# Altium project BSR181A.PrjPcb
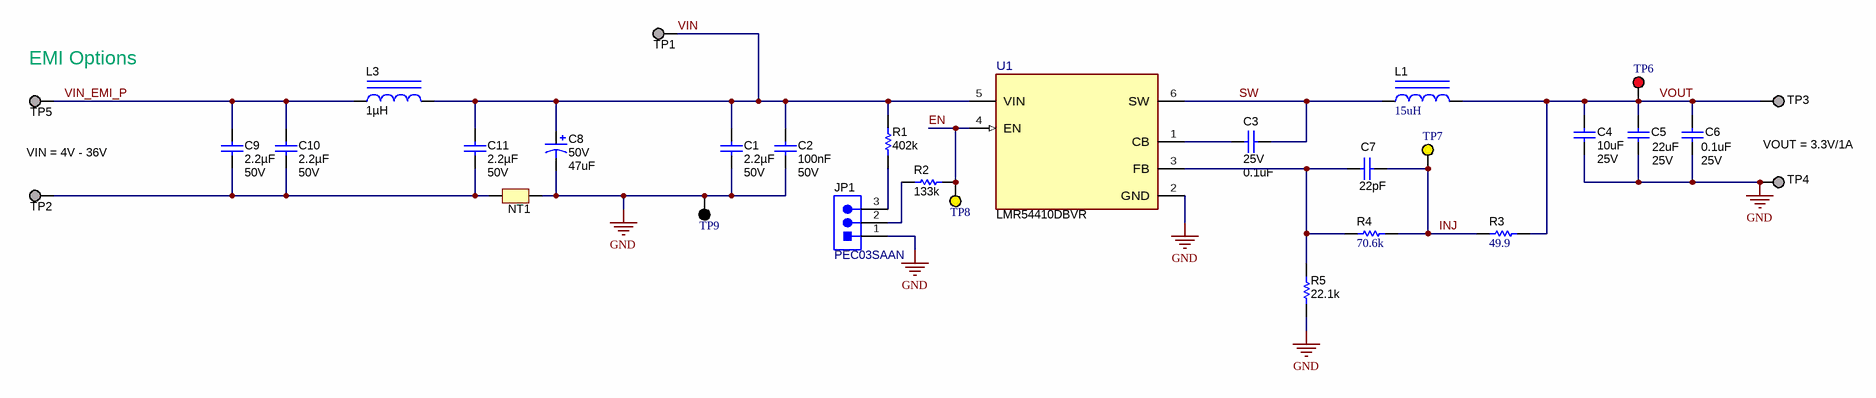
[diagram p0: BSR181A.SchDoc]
CopyrightYear: 2021; PCB_Layout: ElenaGao; PCB_Rev: A1; PRJ_Customer: ENG; PRJ_Engineer: ElenaGao; PRJ_Number: BSR181A; PRJ_Title: LMR54410EVM; SCH_Rev: A1; TechSupport: http://www.ti.com/support; TID: N/A
2 sheets, 46 parts. Net scope: global (net labels, ports and power ports of the same name join across sheets).
Board file: BSR181A.PcbDoc
Sheets:
  BSR181A.SchDoc
  BSR181A_Hardware.SchDoc

## Sheet BSR181A.SchDoc
size 431 x 279 mm; Date: Not shown in title block; ApprovedBy: Not shown in title block; CheckedBy: Not shown in title block; Author: Not shown in title block; CompanyName: Not shown in title block; Engineer: Not shown in title block; Organization: Not shown in title block; Address1: Not shown in title block; Address2: Not shown in title block; Address3: Not shown in title block; Address4: Not shown in title block; DocumentNumber: 2; Revision: Use project parameter SCH_Rev; SheetNumber: 1; SheetTotal: 2; PageSetup: Record=PageOptions¦CenterHorizontal=True¦CenterVertical=True¦PrintScale=1.00¦XCorrection=1.00¦YCorrection=1.00¦PrintKind=0¦BorderSize=5000000¦LeftOffset=0¦BottomOffset=0¦Orientation=2¦PaperLength=1000¦PaperWidth=1000¦Scale=100¦PaperSource=15¦PrintQuality=600¦MediaType=1¦DitherType=10¦PaperKind=Letter¦PrintScaleMode=1

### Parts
C1  Cap_F: 2.2µF  VDC_V: 50V  [0805]  (hidden comment: CGA4J3X7R1H225K125AB)
C2  Cap_F: 100nF  VDC_V: 50V  [0603]  (hidden comment: GCM188R71H104KA57D)
C3  VDC_V: 25V  ValueDisplayed: 0.1uF  [0402S]  (hidden comment: GRM155R71E104KE14D)
C4  Cap_F: 10uF  VDC_V: 25V  [0805]  (hidden comment: GRM21BZ71E106KE15L)
C5  VDC_V: 25V  ValueDisplayed: 22uF  [1812_280]  (hidden comment: CGA8P1X7R1E226M250KC)
C6  Value2: 25V  ValueDisplayed: 0.1uF  [0603]  (hidden comment: C1608X7R1E104K080AA)
C7  ValueDisplayed: 22pF  [0603]  (hidden comment: GRM1885C1H220JA01D)
C8  VDC_V: 50V  ValueDisplayed: 47uF  [CAPSMT_62_F80]  (hidden comment: EMVY500ADA470MF80G)
C9  Cap_F: 2.2µF  VDC_V: 50V  [0805_HV]  (hidden comment: CGA4J3X7R1H225K125AB)
C10  Cap_F: 2.2µF  VDC_V: 50V  [0805_HV]  (hidden comment: CGA4J3X7R1H225K125AB)
C11  Cap_F: 2.2µF  VDC_V: 50V  [0805_HV]  (hidden comment: CGA4J3X7R1H225K125AB)
JP1  PEC03SAAN  [CONN_PEC03SAAN]
L1  ValueDisplayed: 15uH  [WE-LHMI_7050]  (hidden comment: 74437349150)
L3  ValueDisplayed: 1µH  [DFE201612E]  (hidden comment: DFE201612E-1R0M=P2)
NT1  Net-Tie  [Net-Tie_50milWide_30milLong]  (value not drawn)  (net tie, no BOM)
R1  ValueDisplayed: 402k  [0603S]  (hidden comment: CRCW0603402KFKEA)
R2  ValueDisplayed: 133k  [0603S]  (hidden comment: CRCW0603133KFKEA)
R3  ValueDisplayed: 49.9  [0603]  (hidden comment: Resistor)
R4  ValueDisplayed: 70.6k  [0603]  (hidden comment: RT0603BRD0770K6L)
R5  ValueDisplayed: 22.1k  [0603]  (hidden comment: RC0603FR-0722K1L)
TP1  1502-2  [Keystone1502-2]  (value not drawn)
TP2  1502-2  [Keystone1502-2]  (value not drawn)
TP3  1502-2  [Keystone1502-2]  (value not drawn)
TP4  1502-2  [Keystone1502-2]  (value not drawn)
TP5  1502-2  [Keystone1502-2]  (value not drawn)
TP6  5010  [Keystone5010]  (value not drawn)
TP7  5014  [Keystone5014]  (value not drawn)
TP8  5014  [Keystone5014]  (value not drawn)
TP9  5011  [Keystone5011]  (value not drawn)
U1  LMR54410DBVR  [DBV0006A-MFG]

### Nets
GND: C1.2 C2.2 C4.2 C5.2 C6.2 C8.2(-) JP1.1 NT1.2 R5.1 TP4.1 TP9.1 U1.2(GND)
EN: R2.1 TP8.1 U1.4(EN)
INJ: C7.2 R3.2 R4.2 TP7.1
SW: C3.1 L1.1 U1.6(SW)
VIN: C1.1 C2.1 C8.1(+) C11.1 L3.2 R1.2 TP1.1 U1.5(VIN)
VIN_EMI_P: C9.1 C10.1 L3.1 TP5.1
VOUT: C4.1 C5.1 C6.1 L1.2 R3.1 TP3.1 TP6.1
NetC3_2: C3.2 U1.1(CB)
NetC7_1: C7.1 R4.1 R5.2 U1.3(FB)
NetC9_2: C9.2 C10.2 C11.2 NT1.1 TP2.1
NetJP1_2: JP1.2 R2.2
NetJP1_3: JP1.3 R1.1

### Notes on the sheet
- (near TP5) EMI Options
- VIN = 4V - 36V
- VOUT = 3.3V/1A

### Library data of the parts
C1 = CMP-0007977-2: CAP, CERM, 2.2 uF, 50 V, +/- 10%, X7R, AEC-Q200 Grade 1, 0805; Manufacturer: TDK; TaMin_C: -55°C; ESR_ohm: 3.288m; Polarized: N; SizeAreaWB_mm2: 6.75; Value1: 0.003288 ohm; U/M: EA; Value: 2.2uF; TaMax_C: 125°C; SizeZ_mm: 1.45; SizeX_mm: 2; SizeY_mm: 1.25; SizeArea_mm2: 2.5; AEC Qualified: Y; IRMS_A: 3.60029A; AEC Grade: 1; AEC Category: Q200
C2 = CMP-0007144-2: CAP, CERM, 0.1 uF, 50 V, +/- 10%, X7R, 0603; Manufacturer: MuRata; TaMin_C: -55°C; ESR_ohm: 0.02; Polarized: N; SizeAreaWB_mm2: 4.68; Value1: 0.02 ohm; U/M: EA; Value: 0.1uF; TaMax_C: 125°C; SizeZ_mm: 1; SizeX_mm: 1.6; SizeY_mm: 0.8; SizeArea_mm2: 1.28; IRMS_A: 1.84A; AEC Category: Q200
C3 = CMP-0006659-1: CAP, CERM, 0.1 uF, 25 V, +/- 10%, X7R, 0402; Manufacturer: MuRata; TaMin_C: -55°C; Polarized: N; SizeAreaWB_mm2: 3; Value1: Unknown; U/M: EA; Value: 0.1uF; TaMax_C: 125°C; SizeZ_mm: 0.6; SizeX_mm: 1; SizeY_mm: 0.5; Cap_Case: 0402; Cap_F: 100nF; AEC Category: Q200
C4 = CMP-0008378-2: CAP, CERM, 10 uF, 25 V, +/- 10%, X7R, 0805; Manufacturer: MuRata; TaMin_C: -55°C; Polarized: N; SizeAreaWB_mm2: 6.75; Value1: Unknown; U/M: EA; Value: 10uF; TaMax_C: 125°C; SizeZ_mm: 1.45; SizeX_mm: 2; SizeY_mm: 1.25; SizeArea_mm2: 2.5; AEC Category: Q200
C5 = CMP-0009402-2: CAP, CERM, 22 uF, 25 V, +/- 20%, X7R, AEC-Q200 Grade 1,; Manufacturer: TDK; TaMin_C: -55°C; ESR_ohm: 2.434m; Polarized: N; SizeAreaWB_mm2: 23.1; Value1: 0.002434 ohm; U/M: EA; Value: 22uF; TaMax_C: 125°C; SizeZ_mm: 2.8; SizeX_mm: 4.5; SizeY_mm: 3.2; SizeArea_mm2: 14.4; AEC Qualified: Y; Cap_F: 22µF; IRMS_A: 4.91649A; AEC Grade: 1; AEC Category: Q200
C6 = CMP-0007039-1: CAP, CERM, 0.1 uF, 25 V, +/- 10%, X7R, 0603; Manufacturer: TDK; TaMin_C: -55°C; Polarized: N; SizeAreaWB_mm2: 4.68; Value1: Unknown; U/M: EA; Value: 0.1uF; TaMax_C: 125°C; SizeZ_mm: 1; SizeX_mm: 1.6; SizeY_mm: 0.8; SizeArea_mm2: 1.28; Cap_F: 100nF; AEC Category: Q200
C7 = CMP-0007196-4: CAP, CERM, 22 pF, 50 V, +/- 5%, C0G/NP0, 0603; Manufacturer: MuRata; Polarized: N; Value: 22pF; U/M: EA; Value1: Unknown; VDC_V: 50V; TaMin_C: -55°C; TaMax_C: 125°C; SizeAreaWB_mm2: 4.68; SizeZ_mm: 1; SizeX_mm: 1.6; SizeY_mm: 0.8; SizeArea_mm2: 1.28; AEC Category: Q200
C8 = CMP-0011362-1: CAP, AL, 47 uF, 50 V, +/- 20%, 0.6 ohm, SMD; Manufacturer: Chemi-Con; TaMin_C: -55°C; ESR_ohm: 0.6; Polarized: Y; SizeAreaWB_mm2: 73.96; Value1: 0.6 ohm; U/M: EA; Value: 47uF; TaMax_C: 105°C; SizeZ_mm: 7.7; SizeX_mm: 6.6; Cap_Case: F80; SizeArea_mm2: 43.56; CompType: Capacitor; Cap_F: 47µF; IRMS_A: 170mA; AEC Category: Q200
C9-C11 = CMP-0007977-2: CAP, CERM, 2.2 uF, 50 V, +/- 10%, X7R, AEC-Q200 Grade 1, 0805; Manufacturer: TDK; TaMin_C: -55°C; ESR_ohm: 3.288m; Polarized: N; SizeAreaWB_mm2: 6.75; Value1: 0.003288 ohm; U/M: EA; Value: 2.2uF; TaMax_C: 125°C; SizeZ_mm: 1.45; SizeX_mm: 2; SizeY_mm: 1.25; Cap_Case: 0805; SizeArea_mm2: 2.5; AEC Qualified: Y; IRMS_A: 3.60029A; AEC Grade: 1; AEC Category: Q200
JP1 = CMP-0002338-1: Header, 100mil, 3x1, Tin, TH; Manufacturer: Sullins Connector Solutions; CNHeader: TRUE; Current_A: 3A; Green_Lifecycle: Not Set; Shrouded: N; Gender: Male; Green_REACh: Incomplete; Voltage_V: 1.8kV; Row_Count: 1; Pitch_mm: 2.54; CT: FALSE; Cert_UL: Y
L1 = CMP-0064491-2: Inductor, Shielded Drum Core, Powdered Iron, 15 uH, 2.75 A, 0.092 ohm, SMD; Manufacturer: Wurth Elektronik; Isat: 5.5A @ 20% inductance drop; Irms: 2.75A @ 40C rise; Green_Lifecycle: Active; SizeAreaWB_mm2: 73.96; DCR_ohm: 0.092; Green_REACh: Passed; Value: 15uH; Imax_A: 2.75A; SizeZ_mm: 5; SizeX_mm: 6.6; SizeArea_mm2: 43.56; Ind_H: 15µH; AEC Qualified: N; AEC Category: Q200
L3 = CMP-0080773-1: Inductor, Shielded, Metal Composite, 1 µH, 2.9 A, 0.048 ohm, SMD; Manufacturer: MuRata; Isat: 4A @ 30% inductance drop; Irms: 2.9A @ 40C rise; SizeAreaWB_mm2: 7.8; DCR_ohm: 0.048; Value: 1uH; Imax_A: 2.9A; SizeZ_mm: 1.2; SizeX_mm: 2; SizeY_mm: 1.6; SizeArea_mm2: 3.2; AEC Qualified: N; AEC Category: Q200
NT1 = CMP-0078142-2: Single point connection between nets.
R1 = CMP-0022408-4: RES, 402 k, 1%, 0.1 W, AEC-Q200 Grade 0, 0603; Manufacturer: Vishay-Dale; Value: 402k; Power_W: 100mW; Value2: 0.1W; VDC_V: 75V; TempCo: 100 ppm/C; EIA_Code: E96; SizeX_mm: 1.6; SizeY_mm: 0.8; SizeZ_mm: 1; SizeArea_mm2: 1.28; AEC Qualified: Y; AEC Category: Q200; AEC Grade: 0
R2 = CMP-0022038-4: RES, 133 k, 1%, 0.1 W, AEC-Q200 Grade 0, 0603; Manufacturer: Vishay-Dale; Value: 133k; Power_W: 100mW; Value2: 0.1W; VDC_V: 75V; TempCo: 100 ppm/C; EIA_Code: E96; SizeX_mm: 1.6; SizeY_mm: 0.8; SizeZ_mm: 1; SizeArea_mm2: 1.28; AEC Qualified: Y; AEC Category: Q200; AEC Grade: 0
R3 = CMP-0022448-3: RES, 49.9, 1%, 0.1 W, 0603; PartNumber: CRCW060349R9FKEA; Manufacturer: Vishay-Dale; Value: 49.9; Value_Code: 49R9; Power_W: 100mW; Value2: 0.1W; VDC_V: 75V; TempCo: 100 ppm/C; EIA_Code: E96; U/M: EA; SizeX_mm: 1.6; SizeY_mm: 0.8; SizeZ_mm: 1; SizeArea_mm2: 1.28; AEC Category: Q200
R4 = CMP-0024444-2: RES, 70.6 k, 0.1%, 0.1 W, 0603; Manufacturer: Yageo America; Power_W: 100mW; TempCo: 25 ppm/C; Value_Code: 70k6; U/M: EA; Value: 70.6k; EIA_Code: E192; SizeX_mm: 1.6; SizeY_mm: 0.8; SizeZ_mm: 1; Value2: 0.1W; SizeArea_mm2: 1.28; VDC_V: 75V; AEC Category: Q200
R5 = CMP-0022923-5: RES, 22.1 k, 1%, 0.1 W, 0603; Manufacturer: Yageo; Power_W: 100mW; TempCo: 100 ppm/C; Value_Code: 22k1; Value: 22.1k; EIA_Code: E96; SizeX_mm: 1.6; SizeY_mm: 0.8; SizeZ_mm: 1; Value2: 0.1W; SizeArea_mm2: 1.28; AEC Qualified: N; VDC_V: 75V; AEC Category: Q200; SizeAreaWB_mm2: 4.68
TP1-TP5 = CMP-0055113-1: Terminal, Turret, TH, Double; Manufacturer: Keystone; CompType: Turret Terminal; CNHeader: FALSE; Green_Lifecycle: Active; Green_REACh: Passed
TP6 = CMP-0055147-1: Test Point, Multipurpose, Red, TH; Manufacturer: Keystone; CNHeader: FALSE; Green_Lifecycle: Active; Green_REACh: Passed; ContactFinish: Silver; CT: TRUE
TP7 TP8 = CMP-0055151-1: Test Point, Multipurpose, Yellow, TH; Manufacturer: Keystone; CNHeader: FALSE; Green_Lifecycle: Active; Green_REACh: Passed; ContactFinish: Silver; CT: TRUE
TP9 = CMP-0055148-1: Test Point, Multipurpose, Black, TH; Manufacturer: Keystone; CNHeader: FALSE; Green_Lifecycle: Active; Green_REACh: Passed; ContactFinish: Silver; CT: TRUE
U1 = CMP-0093105-2: Buck Converter, Adjustable, 4V-36V Input, 1-28V 1A Output, SOT23-6; Manufacturer: Texas Instruments; SizeZ_mm: 1.45mm; Max Supply Voltage: 36V; Standoff Height: 0mm; Min Supply Voltage: 4V; Number Of Outputs: 1; TJmax_C: +150°C; Nominal Supply Current: 80uA; Max Duty Cycle: 98%; CompType: IC; Switching Frequency: 700kHz; AEC Qualified: No; Output Type: AdjustableProgrammable; AEC Category: Q200

## Sheet BSR181A_Hardware.SchDoc
size 431 x 279 mm; Date: Not shown in title block; ApprovedBy: Not shown in title block; CheckedBy: Not shown in title block; Author: Not shown in title block; CompanyName: Not shown in title block; Engineer: Not shown in title block; Organization: Not shown in title block; Address1: Not shown in title block; Address2: Not shown in title block; Address3: Not shown in title block; Address4: Not shown in title block; DocumentNumber: 1; Revision: Use project parameter SCH_Rev; SheetNumber: 2; SheetTotal: 5; PageSetup: Record=PageOptions¦CenterHorizontal=True¦CenterVertical=True¦PrintScale=1.00¦XCorrection=1.00¦YCorrection=1.00¦PrintKind=0¦BorderSize=5000000¦LeftOffset=0¦BottomOffset=0¦Orientation=2¦PaperLength=1000¦PaperWidth=1000¦Scale=100¦PaperSource=15¦PrintQuality=600¦MediaType=1¦DitherType=10¦PaperKind=Letter¦PrintScaleMode=1
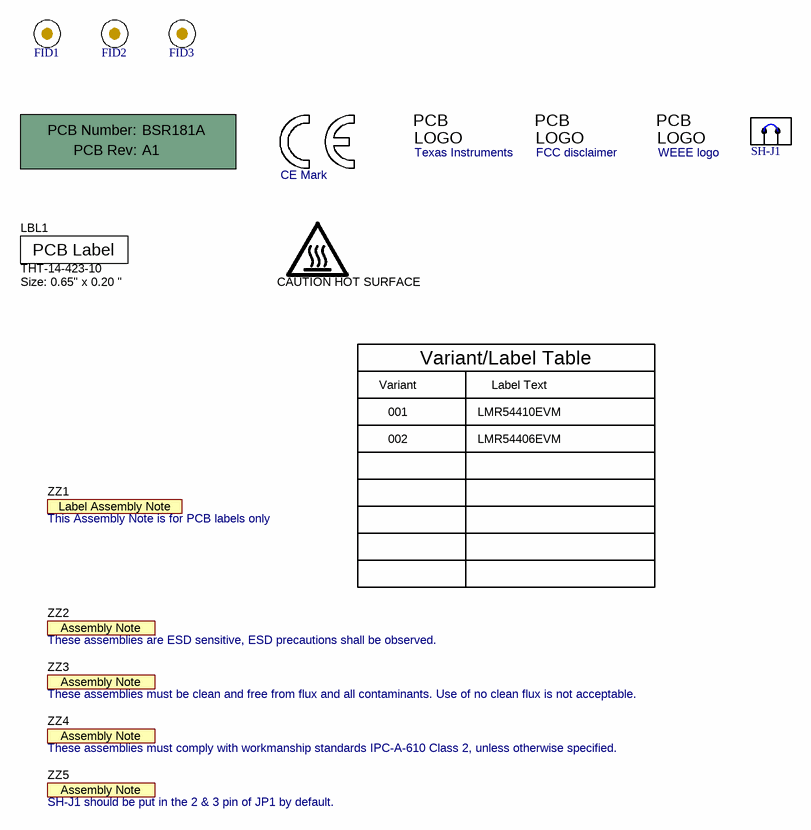
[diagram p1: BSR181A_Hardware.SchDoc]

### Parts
!PCB1  Printed Circuit Board  (value not drawn)  (mechanical)
FID1  Fiducial  [Fiducial10-30]  (value not drawn)
FID2  Fiducial  [Fiducial10-30]  (value not drawn)
FID3  Fiducial  [Fiducial10-30]  (value not drawn)
LBL1  THT-14-423-10  Note: Size: 0.65" x 0.20 "  [Label_650x200]
Logo1  CE Mark  [CE_Mark_5mm]  (no BOM)
Logo2  Texas Instruments  [TI_Horizontal_Overlay_Medium]  (no BOM)
Logo3  FCC disclaimer  [FCC_disclaimer]  (no BOM)
Logo4  WEEE logo  [WEEE_Minimum]  (no BOM)
LOGO5  CAUTION HOT SURFACE  [IEC_HotSurface_Small]  (no BOM)
SH-J1  SNT-100-BK-G  [SNT-100-BK-G]  (value not drawn)
ZZ1  This Assembly Note is for PCB labels only  [AssemblyNoteLabel]  (no BOM)
ZZ2  These assemblies are ESD sensitive, ESD precautions shall be observed.  [AssemblyNote]  (no BOM)
ZZ3  These assemblies must be clean and free from flux and all contaminants. Use of no clean flux is not acceptable.  [AssemblyNote]  (no BOM)
ZZ4  These assemblies must comply with workmanship standards IPC-A-610 Class 2, unless otherwise specified.  [AssemblyNote]  (no BOM)
ZZ5  SH-J1 should be put in the 2 & 3 pin of JP1 by default.  [AssemblyNote]  (no BOM)

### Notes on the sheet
- Variant
- Variant/Label Table
- Label Text
- 001
- 002
- LMR54410EVM
- LMR54406EVM

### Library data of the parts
!PCB1 = CMP-0003618-2: Manufacturer: Any; PartNumber: BSR181A
FID1-FID3 = CMP-0077181-1: Fiducial mark.  There is nothing to buy or mount.
LBL1 = CMP-0003625-1: Thermal Transfer Printable Labels, 0.650" W x 0.200" H - 10,000 per roll; Manufacturer: Brady; CompType: Label
Logo1 = CMP-0074844-1: SymbolCreator: a0412235
Logo2 = CMP-0074838-1: Texas Instrument Corporate Signature; SymbolCreator: a0412235; Lib Reference: TI_Logo
Logo3 = CMP-0074847-1: FCC_disclaimer
Logo4 = CMP-0074769-1
LOGO5 = CMP-0074837-1: IEC 61010-1 Hot Surface Warning; Library Reference: IEC_HotSurface; SymbolCreator: a0412235
SH-J1 = CMP-0003623-3: Shunt, 100mil, Gold plated, Black; Manufacturer: Samtec; Alternate Manufacturer: 3M; Alternate PartNumber: 969102-0000-DA; Value: 1x2; Note: You can "mate" this to a header by matching the designator.  i.e. use SH-J3 for header J3
ZZ1 = CMP-0003616-3
ZZ2 = CMP-0077236-1
ZZ3 = CMP-0077237-1
ZZ4 = CMP-0077238-1
ZZ5 = CMP-0077238-1: These assemblies must comply with workmanship standards IPC-A-610 Class 2, unless otherwise specified.

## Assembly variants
001: not fitted FID1 FID2 FID3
